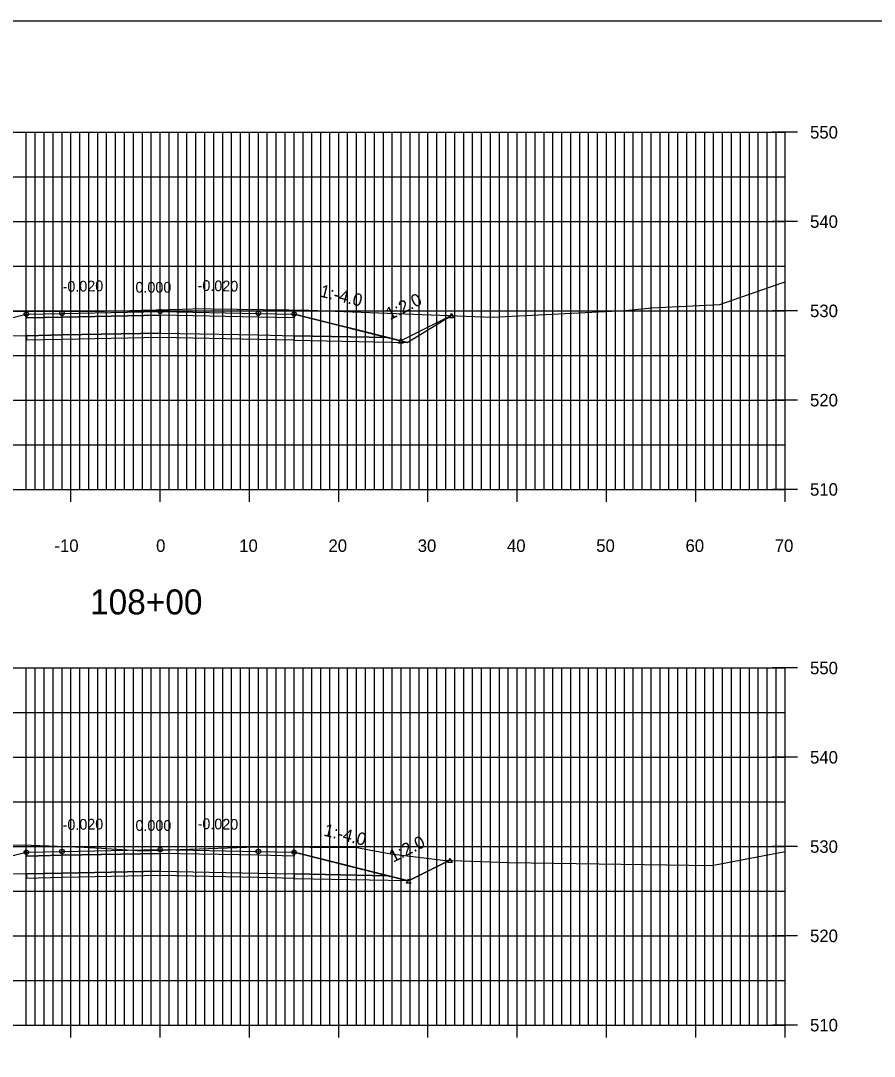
# Model space of a CAD drawing. Extents: x 1509063 to 1512863, y 401160 to 402918.
# Drawn here: x 1512247.1 to 1512342.7, y 402346.1 to 402462.1 of the extents above; entities that cross this region are included whole.
import ezdxf

# ---------------------------------------------------------------- set-up
doc = ezdxf.new("R2010")
doc.units = 0
for name, color, linetype in [('DD_P', 7, 'Continuous'), ('LCUT_P', 7, 'Continuous'), ('NBL1', 7, 'Continuous'), ('PET_P', 7, 'Continuous'), ('PRC', 7, 'Continuous'), ('PSP_P', 7, 'Continuous'), ('RBS_P', 7, 'Continuous'), ('XAX_P', 7, 'Continuous'), ('XAXTIC_P', 7, 'Continuous'), ('XAXTXT_P_T', 7, 'Continuous'), ('XGL_P', 7, 'Continuous'), ('XSL1_P', 7, 'Continuous'), ('XSL1_P_T', 7, 'Continuous'), ('XSL2_P', 7, 'Continuous'), ('XSL3_P', 7, 'Continuous'), ('XSLOG', 7, 'Continuous')]:
    doc.layers.add(name, color=color, linetype=linetype)

msp = doc.modelspace()

# ---------------------------------------------------------------- linework, layer by layer
at = {"layer": 'DD_P'}
for points in [[(1512232.04, 402429.89), (1512238.17, 402426.83), (1512247.73, 402429.22)], [(1512277.73, 402429.22), (1512290.41, 402426.05)], [(1512295.35, 402429.06), (1512289.69, 402426.23), (1512290.41, 402426.05)], [(1512222.64, 402369.99), (1512237.29, 402366.33), (1512247.73, 402368.94)], [(1512290.41, 402365.77), (1512277.73, 402368.94)], [(1512295.19, 402368.04), (1512290.56, 402365.73), (1512290.41, 402365.77)]]:
    msp.add_lwpolyline(points, dxfattribs=at)
for points in [[(1512289.69, 402426.48), (1512289.94, 402425.98), (1512289.44, 402425.98)], [(1512290.56, 402365.98), (1512290.81, 402365.48), (1512290.31, 402365.48)]]:
    msp.add_lwpolyline(points, close=True, dxfattribs=at)
at = {"layer": 'LCUT_P'}
for points in [[(1512295.35, 402429.31), (1512295.6, 402428.81), (1512295.1, 402428.81)], [(1512295.19, 402368.29), (1512295.44, 402367.79), (1512294.94, 402367.79)]]:
    msp.add_lwpolyline(points, close=True, dxfattribs=at)
at = {"layer": 'NBL1'}
msp.add_lwpolyline([(1512502.73, 402252.08), (1512182.73, 402252.08), (1512182.73, 402462.08), (1512502.73, 402462.08)], close=True, dxfattribs=at)
at = {"layer": 'PET_P'}
for centre in [(1512251.73, 402429.3), (1512273.73, 402429.3), (1512251.73, 402369.02), (1512273.73, 402369.02)]:
    msp.add_circle(centre, 0.25, dxfattribs=at)
at = {"layer": 'PRC'}
for centre in [(1512262.73, 402429.52), (1512262.73, 402369.24)]:
    msp.add_circle(centre, 0.25, dxfattribs=at)
at = {"layer": 'PSP_P'}
for centre in [(1512247.73, 402429.22), (1512277.73, 402429.22), (1512247.73, 402368.94), (1512277.73, 402368.94)]:
    msp.add_circle(centre, 0.25, dxfattribs=at)
at = {"layer": 'RBS_P'}
for points in [[(1512247.73, 402429.22), (1512247.73, 402429.47), (1512247.73, 402429.22), (1512247.48, 402429.22), (1512247.73, 402429.22), (1512247.73, 402428.97), (1512247.73, 402429.22), (1512247.98, 402429.22)], [(1512277.73, 402429.22), (1512277.73, 402429.47), (1512277.73, 402429.22), (1512277.48, 402429.22), (1512277.73, 402429.22), (1512277.73, 402428.97), (1512277.73, 402429.22), (1512277.98, 402429.22)], [(1512247.73, 402368.94), (1512247.73, 402369.19), (1512247.73, 402368.94), (1512247.48, 402368.94), (1512247.73, 402368.94), (1512247.73, 402368.69), (1512247.73, 402368.94), (1512247.98, 402368.94)], [(1512277.73, 402368.94), (1512277.73, 402369.19), (1512277.73, 402368.94), (1512277.48, 402368.94), (1512277.73, 402368.94), (1512277.73, 402368.69), (1512277.73, 402368.94), (1512277.98, 402368.94)]]:
    msp.add_lwpolyline(points, dxfattribs=at)
for points in [[(1512247.8, 402428.8), (1512251.73, 402428.88), (1512262.72, 402429.1), (1512262.72, 402427.1), (1512251.73, 402426.88), (1512247.8, 402426.8), (1512237.22, 402426.59), (1512247.73, 402429.22), (1512247.73, 402429.22)], [(1512262.72, 402429.1), (1512262.72, 402427.1), (1512273.73, 402426.88), (1512277.73, 402426.8), (1512288.24, 402426.59), (1512277.73, 402429.22), (1512277.73, 402428.8), (1512273.73, 402428.88)], [(1512247.8, 402368.52), (1512251.73, 402368.6), (1512262.72, 402368.82), (1512262.72, 402366.82), (1512251.73, 402366.6), (1512247.8, 402366.52), (1512237.22, 402366.31), (1512247.73, 402368.94), (1512247.73, 402368.94)], [(1512262.72, 402368.82), (1512262.72, 402366.82), (1512273.73, 402366.6), (1512277.73, 402366.52), (1512288.24, 402366.31), (1512277.73, 402368.94), (1512277.73, 402368.52), (1512273.73, 402368.6)]]:
    msp.add_lwpolyline(points, close=True, dxfattribs=at)
at = {"layer": 'XAX_P'}
for p, q in [((1512262.73, 402409.58), (1512262.73, 402449.58)), ((1512332.73, 402409.58), (1512332.73, 402449.58)), ((1512192.73, 402409.58), (1512332.73, 402409.58)), ((1512262.73, 402349.58), (1512262.73, 402389.58)), ((1512332.73, 402349.58), (1512332.73, 402389.58)), ((1512192.73, 402349.58), (1512332.73, 402349.58))]:
    msp.add_line(p, q, dxfattribs=at)
at = {"layer": 'XAXTIC_P'}
for p, q in [((1512261.33, 402449.58), (1512264.13, 402449.58)), ((1512334.13, 402449.58), (1512331.33, 402449.58)), ((1512261.33, 402439.58), (1512264.13, 402439.58)), ((1512334.13, 402439.58), (1512331.33, 402439.58)), ((1512261.33, 402429.58), (1512264.13, 402429.58)), ((1512334.13, 402429.58), (1512331.33, 402429.58)), ((1512261.33, 402419.58), (1512264.13, 402419.58)), ((1512334.13, 402419.58), (1512331.33, 402419.58)), ((1512252.73, 402408.18), (1512252.73, 402410.98)), ((1512262.73, 402408.18), (1512262.73, 402410.98)), ((1512272.73, 402408.18), (1512272.73, 402410.98)), ((1512282.73, 402408.18), (1512282.73, 402410.98)), ((1512292.73, 402408.18), (1512292.73, 402410.98)), ((1512302.73, 402408.18), (1512302.73, 402410.98)), ((1512312.73, 402408.18), (1512312.73, 402410.98)), ((1512322.73, 402408.18), (1512322.73, 402410.98)), ((1512332.73, 402408.18), (1512332.73, 402410.98)), ((1512261.33, 402409.58), (1512264.13, 402409.58)), ((1512334.13, 402409.58), (1512331.33, 402409.58)), ((1512261.33, 402389.58), (1512264.13, 402389.58)), ((1512334.13, 402389.58), (1512331.33, 402389.58)), ((1512261.33, 402379.58), (1512264.13, 402379.58)), ((1512334.13, 402379.58), (1512331.33, 402379.58)), ((1512261.33, 402369.58), (1512264.13, 402369.58)), ((1512334.13, 402369.58), (1512331.33, 402369.58)), ((1512261.33, 402359.58), (1512264.13, 402359.58)), ((1512334.13, 402359.58), (1512331.33, 402359.58)), ((1512252.73, 402348.18), (1512252.73, 402350.98)), ((1512262.73, 402348.18), (1512262.73, 402350.98)), ((1512272.73, 402348.18), (1512272.73, 402350.98)), ((1512282.73, 402348.18), (1512282.73, 402350.98)), ((1512292.73, 402348.18), (1512292.73, 402350.98)), ((1512302.73, 402348.18), (1512302.73, 402350.98)), ((1512312.73, 402348.18), (1512312.73, 402350.98)), ((1512322.73, 402348.18), (1512322.73, 402350.98)), ((1512332.73, 402348.18), (1512332.73, 402350.98)), ((1512261.33, 402349.58), (1512264.13, 402349.58)), ((1512334.13, 402349.58), (1512331.33, 402349.58))]:
    msp.add_line(p, q, dxfattribs=at)
at = {"layer": 'XGL_P'}
for p, q in [((1512192.73, 402449.58), (1512332.73, 402449.58)), ((1512247.73, 402409.58), (1512247.73, 402449.58)), ((1512248.73, 402409.58), (1512248.73, 402449.58)), ((1512249.73, 402409.58), (1512249.73, 402449.58)), ((1512250.73, 402409.58), (1512250.73, 402449.58)), ((1512251.73, 402409.58), (1512251.73, 402449.58)), ((1512252.73, 402409.58), (1512252.73, 402449.58)), ((1512253.73, 402409.58), (1512253.73, 402449.58)), ((1512254.73, 402409.58), (1512254.73, 402449.58)), ((1512255.73, 402409.58), (1512255.73, 402449.58)), ((1512256.73, 402409.58), (1512256.73, 402449.58)), ((1512257.73, 402409.58), (1512257.73, 402449.58)), ((1512258.73, 402409.58), (1512258.73, 402449.58)), ((1512259.73, 402409.58), (1512259.73, 402449.58)), ((1512260.73, 402409.58), (1512260.73, 402449.58)), ((1512261.73, 402409.58), (1512261.73, 402449.58)), ((1512262.73, 402409.58), (1512262.73, 402449.58)), ((1512263.73, 402409.58), (1512263.73, 402449.58)), ((1512264.73, 402409.58), (1512264.73, 402449.58)), ((1512265.73, 402409.58), (1512265.73, 402449.58)), ((1512266.73, 402409.58), (1512266.73, 402449.58)), ((1512267.73, 402409.58), (1512267.73, 402449.58)), ((1512268.73, 402409.58), (1512268.73, 402449.58)), ((1512269.73, 402409.58), (1512269.73, 402449.58)), ((1512270.73, 402409.58), (1512270.73, 402449.58)), ((1512271.73, 402409.58), (1512271.73, 402449.58)), ((1512272.73, 402409.58), (1512272.73, 402449.58)), ((1512273.73, 402409.58), (1512273.73, 402449.58)), ((1512274.73, 402409.58), (1512274.73, 402449.58)), ((1512275.73, 402409.58), (1512275.73, 402449.58)), ((1512276.73, 402409.58), (1512276.73, 402449.58)), ((1512277.73, 402409.58), (1512277.73, 402449.58)), ((1512278.73, 402409.58), (1512278.73, 402449.58)), ((1512279.73, 402409.58), (1512279.73, 402449.58)), ((1512280.73, 402409.58), (1512280.73, 402449.58)), ((1512281.73, 402409.58), (1512281.73, 402449.58)), ((1512282.73, 402409.58), (1512282.73, 402449.58)), ((1512283.73, 402409.58), (1512283.73, 402449.58)), ((1512284.73, 402409.58), (1512284.73, 402449.58)), ((1512285.73, 402409.58), (1512285.73, 402449.58)), ((1512286.73, 402409.58), (1512286.73, 402449.58)), ((1512287.73, 402409.58), (1512287.73, 402449.58)), ((1512288.73, 402409.58), (1512288.73, 402449.58)), ((1512289.73, 402409.58), (1512289.73, 402449.58)), ((1512290.73, 402409.58), (1512290.73, 402449.58)), ((1512291.73, 402409.58), (1512291.73, 402449.58)), ((1512292.73, 402409.58), (1512292.73, 402449.58)), ((1512293.73, 402409.58), (1512293.73, 402449.58)), ((1512294.73, 402409.58), (1512294.73, 402449.58)), ((1512295.73, 402409.58), (1512295.73, 402449.58)), ((1512296.73, 402409.58), (1512296.73, 402449.58)), ((1512297.73, 402409.58), (1512297.73, 402449.58)), ((1512298.73, 402409.58), (1512298.73, 402449.58)), ((1512299.73, 402409.58), (1512299.73, 402449.58)), ((1512300.73, 402409.58), (1512300.73, 402449.58)), ((1512301.73, 402409.58), (1512301.73, 402449.58)), ((1512302.73, 402409.58), (1512302.73, 402449.58)), ((1512303.73, 402409.58), (1512303.73, 402449.58)), ((1512304.73, 402409.58), (1512304.73, 402449.58)), ((1512305.73, 402409.58), (1512305.73, 402449.58)), ((1512306.73, 402409.58), (1512306.73, 402449.58)), ((1512307.73, 402409.58), (1512307.73, 402449.58)), ((1512308.73, 402409.58), (1512308.73, 402449.58)), ((1512309.73, 402409.58), (1512309.73, 402449.58)), ((1512310.73, 402409.58), (1512310.73, 402449.58)), ((1512311.73, 402409.58), (1512311.73, 402449.58)), ((1512312.73, 402409.58), (1512312.73, 402449.58)), ((1512313.73, 402409.58), (1512313.73, 402449.58)), ((1512314.73, 402409.58), (1512314.73, 402449.58)), ((1512315.73, 402409.58), (1512315.73, 402449.58)), ((1512316.73, 402409.58), (1512316.73, 402449.58)), ((1512317.73, 402409.58), (1512317.73, 402449.58)), ((1512318.73, 402409.58), (1512318.73, 402449.58)), ((1512319.73, 402409.58), (1512319.73, 402449.58)), ((1512320.73, 402409.58), (1512320.73, 402449.58)), ((1512321.73, 402409.58), (1512321.73, 402449.58)), ((1512322.73, 402409.58), (1512322.73, 402449.58)), ((1512323.73, 402409.58), (1512323.73, 402449.58)), ((1512324.73, 402409.58), (1512324.73, 402449.58)), ((1512325.73, 402409.58), (1512325.73, 402449.58)), ((1512326.73, 402409.58), (1512326.73, 402449.58)), ((1512327.73, 402409.58), (1512327.73, 402449.58)), ((1512328.73, 402409.58), (1512328.73, 402449.58)), ((1512329.73, 402409.58), (1512329.73, 402449.58)), ((1512330.73, 402409.58), (1512330.73, 402449.58)), ((1512331.73, 402409.58), (1512331.73, 402449.58)), ((1512332.73, 402409.58), (1512332.73, 402449.58)), ((1512192.73, 402444.58), (1512332.73, 402444.58)), ((1512192.73, 402439.58), (1512332.73, 402439.58)), ((1512192.73, 402434.58), (1512332.73, 402434.58)), ((1512192.73, 402429.58), (1512332.73, 402429.58)), ((1512192.73, 402424.58), (1512332.73, 402424.58)), ((1512192.73, 402419.58), (1512332.73, 402419.58)), ((1512192.73, 402414.58), (1512332.73, 402414.58)), ((1512192.73, 402409.58), (1512332.73, 402409.58)), ((1512192.73, 402389.58), (1512332.73, 402389.58)), ((1512247.73, 402349.58), (1512247.73, 402389.58)), ((1512248.73, 402349.58), (1512248.73, 402389.58)), ((1512249.73, 402349.58), (1512249.73, 402389.58)), ((1512250.73, 402349.58), (1512250.73, 402389.58)), ((1512251.73, 402349.58), (1512251.73, 402389.58)), ((1512252.73, 402349.58), (1512252.73, 402389.58)), ((1512253.73, 402349.58), (1512253.73, 402389.58)), ((1512254.73, 402349.58), (1512254.73, 402389.58)), ((1512255.73, 402349.58), (1512255.73, 402389.58)), ((1512256.73, 402349.58), (1512256.73, 402389.58)), ((1512257.73, 402349.58), (1512257.73, 402389.58)), ((1512258.73, 402349.58), (1512258.73, 402389.58)), ((1512259.73, 402349.58), (1512259.73, 402389.58)), ((1512260.73, 402349.58), (1512260.73, 402389.58)), ((1512261.73, 402349.58), (1512261.73, 402389.58)), ((1512262.73, 402349.58), (1512262.73, 402389.58)), ((1512263.73, 402349.58), (1512263.73, 402389.58)), ((1512264.73, 402349.58), (1512264.73, 402389.58)), ((1512265.73, 402349.58), (1512265.73, 402389.58)), ((1512266.73, 402349.58), (1512266.73, 402389.58)), ((1512267.73, 402349.58), (1512267.73, 402389.58)), ((1512268.73, 402349.58), (1512268.73, 402389.58)), ((1512269.73, 402349.58), (1512269.73, 402389.58)), ((1512270.73, 402349.58), (1512270.73, 402389.58)), ((1512271.73, 402349.58), (1512271.73, 402389.58)), ((1512272.73, 402349.58), (1512272.73, 402389.58)), ((1512273.73, 402349.58), (1512273.73, 402389.58)), ((1512274.73, 402349.58), (1512274.73, 402389.58)), ((1512275.73, 402349.58), (1512275.73, 402389.58)), ((1512276.73, 402349.58), (1512276.73, 402389.58)), ((1512277.73, 402349.58), (1512277.73, 402389.58)), ((1512278.73, 402349.58), (1512278.73, 402389.58)), ((1512279.73, 402349.58), (1512279.73, 402389.58)), ((1512280.73, 402349.58), (1512280.73, 402389.58)), ((1512281.73, 402349.58), (1512281.73, 402389.58)), ((1512282.73, 402349.58), (1512282.73, 402389.58)), ((1512283.73, 402349.58), (1512283.73, 402389.58)), ((1512284.73, 402349.58), (1512284.73, 402389.58)), ((1512285.73, 402349.58), (1512285.73, 402389.58)), ((1512286.73, 402349.58), (1512286.73, 402389.58)), ((1512287.73, 402349.58), (1512287.73, 402389.58)), ((1512288.73, 402349.58), (1512288.73, 402389.58)), ((1512289.73, 402349.58), (1512289.73, 402389.58)), ((1512290.73, 402349.58), (1512290.73, 402389.58)), ((1512291.73, 402349.58), (1512291.73, 402389.58)), ((1512292.73, 402349.58), (1512292.73, 402389.58)), ((1512293.73, 402349.58), (1512293.73, 402389.58)), ((1512294.73, 402349.58), (1512294.73, 402389.58)), ((1512295.73, 402349.58), (1512295.73, 402389.58)), ((1512296.73, 402349.58), (1512296.73, 402389.58)), ((1512297.73, 402349.58), (1512297.73, 402389.58)), ((1512298.73, 402349.58), (1512298.73, 402389.58)), ((1512299.73, 402349.58), (1512299.73, 402389.58)), ((1512300.73, 402349.58), (1512300.73, 402389.58)), ((1512301.73, 402349.58), (1512301.73, 402389.58)), ((1512302.73, 402349.58), (1512302.73, 402389.58)), ((1512303.73, 402349.58), (1512303.73, 402389.58)), ((1512304.73, 402349.58), (1512304.73, 402389.58)), ((1512305.73, 402349.58), (1512305.73, 402389.58)), ((1512306.73, 402349.58), (1512306.73, 402389.58)), ((1512307.73, 402349.58), (1512307.73, 402389.58)), ((1512308.73, 402349.58), (1512308.73, 402389.58)), ((1512309.73, 402349.58), (1512309.73, 402389.58)), ((1512310.73, 402349.58), (1512310.73, 402389.58)), ((1512311.73, 402349.58), (1512311.73, 402389.58)), ((1512312.73, 402349.58), (1512312.73, 402389.58)), ((1512313.73, 402349.58), (1512313.73, 402389.58)), ((1512314.73, 402349.58), (1512314.73, 402389.58)), ((1512315.73, 402349.58), (1512315.73, 402389.58)), ((1512316.73, 402349.58), (1512316.73, 402389.58)), ((1512317.73, 402349.58), (1512317.73, 402389.58)), ((1512318.73, 402349.58), (1512318.73, 402389.58)), ((1512319.73, 402349.58), (1512319.73, 402389.58)), ((1512320.73, 402349.58), (1512320.73, 402389.58)), ((1512321.73, 402349.58), (1512321.73, 402389.58)), ((1512322.73, 402349.58), (1512322.73, 402389.58)), ((1512323.73, 402349.58), (1512323.73, 402389.58)), ((1512324.73, 402349.58), (1512324.73, 402389.58)), ((1512325.73, 402349.58), (1512325.73, 402389.58)), ((1512326.73, 402349.58), (1512326.73, 402389.58)), ((1512327.73, 402349.58), (1512327.73, 402389.58)), ((1512328.73, 402349.58), (1512328.73, 402389.58)), ((1512329.73, 402349.58), (1512329.73, 402389.58)), ((1512330.73, 402349.58), (1512330.73, 402389.58)), ((1512331.73, 402349.58), (1512331.73, 402389.58)), ((1512332.73, 402349.58), (1512332.73, 402389.58)), ((1512192.73, 402384.58), (1512332.73, 402384.58)), ((1512192.73, 402379.58), (1512332.73, 402379.58)), ((1512192.73, 402374.58), (1512332.73, 402374.58)), ((1512192.73, 402369.58), (1512332.73, 402369.58)), ((1512192.73, 402364.58), (1512332.73, 402364.58)), ((1512192.73, 402359.58), (1512332.73, 402359.58)), ((1512192.73, 402354.58), (1512332.73, 402354.58)), ((1512192.73, 402349.58), (1512332.73, 402349.58))]:
    msp.add_line(p, q, dxfattribs=at)
at = {"layer": 'XSL1_P'}
for points in [[(1512232.04, 402429.89), (1512237.22, 402426.59), (1512238.17, 402426.83), (1512247.73, 402429.22), (1512251.73, 402429.3), (1512262.73, 402429.52), (1512273.73, 402429.3), (1512277.73, 402429.22), (1512288.24, 402426.59), (1512289.69, 402426.23), (1512290.41, 402426.05), (1512295.35, 402429.06)], [(1512222.64, 402369.99), (1512237.22, 402366.31), (1512237.29, 402366.33), (1512247.73, 402368.94), (1512251.73, 402369.02), (1512262.73, 402369.24), (1512273.73, 402369.02), (1512277.73, 402368.94), (1512288.24, 402366.31), (1512290.41, 402365.77), (1512290.56, 402365.73), (1512295.19, 402368.04)]]:
    msp.add_lwpolyline(points, dxfattribs=at)
at = {"layer": 'XSL2_P'}
for points in [[(1512273.73, 402426.38), (1512262.72, 402426.6), (1512251.73, 402426.38), (1512247.8, 402426.3), (1512247.8, 402426.8), (1512251.73, 402426.88), (1512262.72, 402427.1), (1512273.73, 402426.88), (1512277.73, 402426.8), (1512277.73, 402426.3)], [(1512277.73, 402426.8), (1512277.73, 402426.3), (1512290.41, 402426.05), (1512288.24, 402426.59)], [(1512273.73, 402366.1), (1512262.72, 402366.32), (1512251.73, 402366.1), (1512247.8, 402366.02), (1512247.8, 402366.52), (1512251.73, 402366.6), (1512262.72, 402366.82), (1512273.73, 402366.6), (1512277.73, 402366.52), (1512277.73, 402366.02)], [(1512277.73, 402366.52), (1512277.73, 402366.02), (1512290.41, 402365.77), (1512288.24, 402366.31)]]:
    msp.add_lwpolyline(points, close=True, dxfattribs=at)
for points in [[(1512288.24, 402426.59), (1512277.73, 402426.8)], [(1512288.24, 402366.31), (1512277.73, 402366.52)]]:
    msp.add_lwpolyline(points, dxfattribs=at)
at = {"layer": 'XSL3_P'}
for points in [[(1512251.73, 402428.88), (1512247.8, 402428.8), (1512247.73, 402429.22), (1512251.73, 402429.3), (1512262.72, 402429.52), (1512273.73, 402429.3), (1512277.73, 402429.22), (1512277.73, 402428.8), (1512273.73, 402428.88), (1512262.72, 402429.1)], [(1512251.73, 402368.6), (1512247.8, 402368.52), (1512247.73, 402368.94), (1512251.73, 402369.02), (1512262.72, 402369.24), (1512273.73, 402369.02), (1512277.73, 402368.94), (1512277.73, 402368.52), (1512273.73, 402368.6), (1512262.72, 402368.82)]]:
    msp.add_lwpolyline(points, close=True, dxfattribs=at)
at = {"layer": 'XSLOG'}
for points in [[(1512192.73, 402430.44), (1512205.89, 402430.43), (1512212.69, 402430.38), (1512230.92, 402429.92), (1512247.59, 402429.52), (1512251.73, 402429.53), (1512255.03, 402429.52), (1512265.18, 402429.77), (1512267.56, 402429.84), (1512268.48, 402429.82), (1512277.14, 402429.69), (1512278.94, 402429.67), (1512279.14, 402429.66), (1512279.37, 402429.65), (1512299.91, 402428.89), (1512314.83, 402429.62), (1512317.82, 402429.91), (1512325.42, 402430.29), (1512331.09, 402432.29), (1512332.73, 402432.82)], [(1512192.73, 402370.4), (1512197, 402370.32), (1512204.5, 402370.19), (1512216.38, 402370.06), (1512223.63, 402369.98), (1512228.71, 402369.92), (1512232.47, 402369.88), (1512236.69, 402369.85), (1512248.26, 402369.74), (1512254.21, 402369.5), (1512254.76, 402369.49), (1512256.16, 402369.41), (1512260.7, 402369.12), (1512272.41, 402369.52), (1512273.05, 402369.55), (1512274.19, 402369.54), (1512284.8, 402369.47), (1512286.32, 402369.18), (1512288.55, 402368.76), (1512294.41, 402368.06), (1512301.75, 402367.81), (1512324.52, 402367.46), (1512332.73, 402369.01)]]:
    msp.add_lwpolyline(points, dxfattribs=at)

# ---------------------------------------------------------------- texts
at = {"layer": 'XAXTXT_P_T'}
for s, height, p in [('550', 1.4, (1512335.53, 402448.88)), ('540', 1.4, (1512335.53, 402438.88)), ('530', 1.4, (1512335.53, 402428.88)), ('520', 1.4, (1512335.53, 402418.88)), ('510', 1.4, (1512335.53, 402408.88)), ('-10', 1.4, (1512250.88, 402402.58)), ('0', 1.4, (1512262.27, 402402.58)), ('10', 1.4, (1512271.58, 402402.58)), ('20', 1.4, (1512281.58, 402402.58)), ('30', 1.4, (1512291.58, 402402.58)), ('40', 1.4, (1512301.58, 402402.58)), ('50', 1.4, (1512311.58, 402402.58)), ('60', 1.4, (1512321.58, 402402.58)), ('70', 1.4, (1512331.58, 402402.58)), ('108+00', 2.8, (1512254.87, 402395.58)), ('550', 1.4, (1512335.53, 402388.88)), ('540', 1.4, (1512335.53, 402378.88)), ('530', 1.4, (1512335.53, 402368.88)), ('520', 1.4, (1512335.53, 402358.88)), ('510', 1.4, (1512335.53, 402348.88))]:
    msp.add_text(s, height=height, dxfattribs=at).set_placement(p)
at = {"layer": 'XSL1_P_T'}
for s, height, rotation, p in [('-0.020', 1.2, 1.142, (1512251.81, 402431.7)), ('0.000', 1.2, 359.9981, (1512259.96, 402431.62)), ('0.000', 1.2, 359.9981, (1512259.96, 402431.62)), ('-0.020', 1.2, 358.8542, (1512266.91, 402431.83)), ('1:-4.0', 1.4, 345.9638, (1512280.53, 402431.2)), ('1:-4.0', 1.4, 345.9638, (1512280.53, 402431.2)), ('1:-4.0', 1.4, 345.9638, (1512280.53, 402431.2)), ('1:2.0', 1.4, 26.5651, (1512288.46, 402428.52)), ('1:2.0', 1.4, 26.5651, (1512288.46, 402428.52)), ('1:2.0', 1.4, 26.5651, (1512288.46, 402428.52)), ('-0.020', 1.2, 1.142, (1512251.81, 402371.42)), ('0.000', 1.2, 359.9981, (1512259.96, 402371.34)), ('0.000', 1.2, 359.9981, (1512259.96, 402371.34)), ('-0.020', 1.2, 358.8542, (1512266.91, 402371.55)), ('1:-4.0', 1.4, 345.9638, (1512280.96, 402370.81)), ('1:-4.0', 1.4, 345.9638, (1512280.96, 402370.81)), ('1:-4.0', 1.4, 345.9638, (1512280.96, 402370.81)), ('1:2.0', 1.4, 26.5651, (1512288.82, 402367.76)), ('1:2.0', 1.4, 26.5651, (1512288.82, 402367.76)), ('1:2.0', 1.4, 26.5651, (1512288.82, 402367.76))]:
    msp.add_text(s, height=height, rotation=rotation, dxfattribs=at).set_placement(p)

doc.saveas('drawing.dxf')
